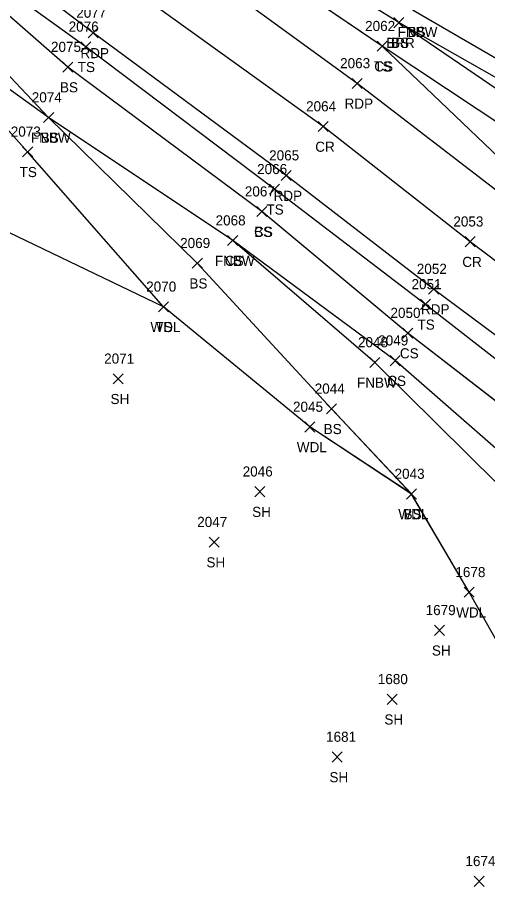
# Model space of a CAD drawing. Extents: x 1415642 to 1422021, y 544543 to 547232.
# Drawn here: x 1415773.3 to 1415866.3, y 546920.1 to 547093.4 of the extents above; entities that cross this region are included whole.
import ezdxf

# ---------------------------------------------------------------- set-up
doc = ezdxf.new("R2010")
doc.units = 0
for name, color, linetype in [('L_A', 7, 'Continuous'), ('L_I', 7, 'Continuous'), ('L_TIC', 7, 'Continuous'), ('LABL', 7, 'Continuous'), ('LAWA', 7, 'Continuous'), ('LELB', 7, 'Continuous'), ('LFNC', 7, 'Continuous'), ('P_A', 7, 'Continuous'), ('P_I', 7, 'Continuous'), ('P_TIC', 7, 'Continuous'), ('PET', 7, 'Continuous'), ('PRC', 7, 'Continuous')]:
    doc.layers.add(name, color=color, linetype=linetype)

msp = doc.modelspace()

# ---------------------------------------------------------------- linework, layer by layer
at = {"layer": 'L_TIC'}
for points in [[(1415847.8, 547091.4), (1415849.8, 547093.4)], [(1415849.8, 547091.4), (1415847.8, 547093.4)], [(1415847.8, 547091.4), (1415849.8, 547093.4)], [(1415849.8, 547091.4), (1415847.8, 547093.4)], [(1415785.82, 547086.62), (1415787.82, 547088.62)], [(1415787.82, 547086.62), (1415785.82, 547088.62)], [(1415844.5, 547086.74), (1415846.5, 547088.74)], [(1415846.5, 547086.74), (1415844.5, 547088.74)], [(1415844.5, 547086.74), (1415846.5, 547088.74)], [(1415846.5, 547086.74), (1415844.5, 547088.74)], [(1415782.27, 547082.61), (1415784.27, 547084.61)], [(1415784.27, 547082.61), (1415782.27, 547084.61)], [(1415778.47, 547072.63), (1415780.47, 547074.63)], [(1415780.47, 547072.63), (1415778.47, 547074.63)], [(1415778.47, 547072.63), (1415780.47, 547074.63)], [(1415780.47, 547072.63), (1415778.47, 547074.63)], [(1415774.31, 547065.85), (1415776.31, 547067.85)], [(1415776.31, 547065.85), (1415774.31, 547067.85)], [(1415823.18, 547058.44), (1415825.18, 547060.44)], [(1415825.18, 547058.44), (1415823.18, 547060.44)], [(1415820.69, 547054.02), (1415822.69, 547056.02)], [(1415822.69, 547054.02), (1415820.69, 547056.02)], [(1415820.69, 547054.02), (1415822.69, 547056.02)], [(1415822.69, 547054.02), (1415820.69, 547056.02)], [(1415814.91, 547048.29), (1415816.91, 547050.29)], [(1415816.91, 547048.29), (1415814.91, 547050.29)], [(1415814.91, 547048.29), (1415816.91, 547050.29)], [(1415816.91, 547048.29), (1415814.91, 547050.29)], [(1415807.9, 547043.81), (1415809.9, 547045.81)], [(1415809.9, 547043.81), (1415807.9, 547045.81)], [(1415801.21, 547035.19), (1415803.21, 547037.19)], [(1415803.21, 547035.19), (1415801.21, 547037.19)], [(1415801.21, 547035.19), (1415803.21, 547037.19)], [(1415803.21, 547035.19), (1415801.21, 547037.19)], [(1415853.08, 547035.67), (1415855.08, 547037.67)], [(1415855.08, 547035.67), (1415853.08, 547037.67)], [(1415849.56, 547029.99), (1415851.56, 547031.99)], [(1415851.56, 547029.99), (1415849.56, 547031.99)], [(1415843.05, 547024.19), (1415845.05, 547026.19)], [(1415845.05, 547024.19), (1415843.05, 547026.19)], [(1415847.06, 547024.54), (1415849.06, 547026.54)], [(1415849.06, 547024.54), (1415847.06, 547026.54)], [(1415792.23, 547020.95), (1415794.23, 547022.95)], [(1415794.23, 547020.95), (1415792.23, 547022.95)], [(1415834.48, 547015.01), (1415836.48, 547017.01)], [(1415836.48, 547015.01), (1415834.48, 547017.01)], [(1415830.18, 547011.42), (1415832.18, 547013.42)], [(1415832.18, 547011.42), (1415830.18, 547013.42)], [(1415820.27, 546998.62), (1415822.27, 547000.62)], [(1415822.27, 546998.62), (1415820.27, 547000.62)], [(1415850.29, 546998.16), (1415852.29, 547000.16)], [(1415852.29, 546998.16), (1415850.29, 547000.16)], [(1415850.29, 546998.16), (1415852.29, 547000.16)], [(1415852.29, 546998.16), (1415850.29, 547000.16)], [(1415811.22, 546988.64), (1415813.22, 546990.64)], [(1415813.22, 546988.64), (1415811.22, 546990.64)], [(1415861.73, 546978.72), (1415863.73, 546980.72)], [(1415863.73, 546978.72), (1415861.73, 546980.72)], [(1415855.85, 546971.2), (1415857.85, 546973.2)], [(1415857.85, 546971.2), (1415855.85, 546973.2)], [(1415846.46, 546957.55), (1415848.46, 546959.55)], [(1415848.46, 546957.55), (1415846.46, 546959.55)], [(1415835.57, 546946.14), (1415837.57, 546948.14)], [(1415837.57, 546946.14), (1415835.57, 546948.14)], [(1415863.72, 546921.55), (1415865.72, 546923.55)], [(1415865.72, 546921.55), (1415863.72, 546923.55)]]:
    msp.add_lwpolyline(points, dxfattribs=at)
at = {"layer": 'LABL'}
for points in [[(1415954.88, 547028.96), (1415919.29, 547048.67), (1415882.22, 547073.43), (1415848.8, 547092.4), (1415822.78, 547108.48), (1415823.18, 547113.64)], [(1415954.88, 547028.97), (1415919.29, 547048.66), (1415882.22, 547073.42), (1415848.8, 547092.4), (1415822.78, 547108.48), (1415823.18, 547113.63)]]:
    msp.add_lwpolyline(points, dxfattribs=at)
at = {"layer": 'LAWA'}
for points in [[(1415914.11, 546834.35), (1415931.31, 546850.74), (1415944.85, 546869.92), (1415908.68, 546903.98), (1415882.09, 546945.44), (1415862.73, 546979.72), (1415851.29, 546999.16), (1415831.18, 547012.42), (1415802.21, 547036.19), (1415763.17, 547054.94), (1415718.14, 547089.46), (1415689.93, 547108.01)], [(1415914.12, 546834.35), (1415931.31, 546850.75), (1415944.86, 546869.92), (1415908.68, 546903.98), (1415882.1, 546945.44), (1415862.73, 546979.72), (1415851.29, 546999.15), (1415831.18, 547012.42), (1415802.2, 547036.19), (1415763.17, 547054.94), (1415718.15, 547089.45), (1415689.93, 547108.01)]]:
    msp.add_lwpolyline(points, dxfattribs=at)
at = {"layer": 'LELB'}
for points in [[(1415821.69, 547055.02), (1415783.27, 547083.61), (1415741.01, 547120.53), (1415723.94, 547132.39), (1415695.54, 547155.33), (1415675.42, 547170.57)], [(1415821.7, 547055.02), (1415783.28, 547083.61), (1415741.01, 547120.53), (1415723.94, 547132.38), (1415695.54, 547155.33), (1415675.42, 547170.56)], [(1415851.29, 546999.16), (1415835.48, 547016.01), (1415808.9, 547044.81), (1415779.47, 547073.63), (1415738.35, 547117.19), (1415722.7, 547128.21), (1415693.4, 547151.97), (1415674.17, 547168.64)], [(1415851.29, 546999.15), (1415835.48, 547016.02), (1415808.9, 547044.81), (1415779.47, 547073.63), (1415738.34, 547117.19), (1415722.7, 547128.21), (1415693.4, 547151.96), (1415674.17, 547168.64)], [(1415802.21, 547036.19), (1415775.31, 547066.85), (1415750.83, 547094.22), (1415733.1, 547115.73), (1415720.57, 547124.98), (1415690.99, 547148.71), (1415672.49, 547166.01)], [(1415802.2, 547036.19), (1415775.31, 547066.86), (1415750.83, 547094.23), (1415733.1, 547115.73), (1415720.57, 547124.98), (1415690.99, 547148.71), (1415672.49, 547166.01)], [(1416091.47, 546896.23), (1416067.28, 546915.33), (1416036.7, 546941.48), (1416008.25, 546963.65), (1415975.6, 546988.56), (1415942.26, 547013.09), (1415909.12, 547036.86), (1415872.92, 547061.56), (1415845.5, 547087.74), (1415809.03, 547112.5), (1415805.73, 547114.89), (1415787.7, 547125.97), (1415788.24, 547129.84), (1415790.68, 547131.85)], [(1416091.47, 546896.23), (1416067.28, 546915.33), (1416036.71, 546941.48), (1416008.26, 546963.65), (1415975.6, 546988.56), (1415942.26, 547013.09), (1415909.12, 547036.86), (1415872.92, 547061.56), (1415845.5, 547087.74), (1415809.04, 547112.5), (1415805.73, 547114.9), (1415787.7, 547125.97), (1415788.24, 547129.84), (1415790.68, 547131.85)], [(1415979.27, 546932.57), (1415964.6, 546940.59), (1415957.63, 546956.7), (1415934.73, 546972.98), (1415912.21, 546991.17), (1415886.95, 547011.09), (1415854.08, 547036.67), (1415824.18, 547059.44), (1415786.82, 547087.62), (1415741.01, 547120.53)], [(1415979.28, 546932.57), (1415964.61, 546940.59), (1415957.63, 546956.7), (1415934.74, 546972.98), (1415912.22, 546991.17), (1415886.96, 547011.09), (1415854.08, 547036.67), (1415824.19, 547059.44), (1415786.82, 547087.62), (1415741.01, 547120.53)], [(1416166.26, 546865.71), (1416159.51, 546874.18), (1416128.86, 546893.05), (1416099.94, 546911.95), (1416080.11, 546927.17), (1416051.61, 546951.27), (1416024.79, 546978.54), (1415989.85, 547005.5), (1415949.92, 547022.61), (1415918.77, 547047.8), (1415880.24, 547071.02), (1415848.8, 547092.4)], [(1416166.26, 546865.71), (1416159.51, 546874.18), (1416128.86, 546893.05), (1416099.95, 546911.94), (1416080.11, 546927.17), (1416051.61, 546951.27), (1416024.79, 546978.54), (1415989.85, 547005.5), (1415949.92, 547022.61), (1415918.78, 547047.8), (1415880.25, 547071.01), (1415848.8, 547092.4)], [(1416210.45, 546810.14), (1416187.24, 546828.5), (1416172.35, 546839.03), (1416162.91, 546845.64), (1416145.69, 546861.76), (1416125.16, 546875.54), (1416093.4, 546901.43), (1416075.19, 546919.9), (1416045.66, 546942.32), (1416039.77, 546946.29), (1416015.88, 546971.97), (1415979.91, 546993.7), (1415946.5, 547018.2), (1415914.22, 547042.27), (1415877.25, 547066.68), (1415845.5, 547087.74)], [(1416210.45, 546810.14), (1416187.24, 546828.5), (1416172.36, 546839.03), (1416162.91, 546845.64), (1416145.7, 546861.76), (1416125.16, 546875.54), (1416093.4, 546901.44), (1416075.18, 546919.9), (1416045.66, 546942.32), (1416039.77, 546946.29), (1416015.88, 546971.97), (1415979.91, 546993.7), (1415946.51, 547018.2), (1415914.22, 547042.27), (1415877.24, 547066.68), (1415845.5, 547087.74)], [(1416200.69, 546756.25), (1416177.76, 546767.63), (1416166.72, 546775.57), (1416158.94, 546780.74), (1416149.8, 546790.95), (1416145.27, 546792.19), (1416135.47, 546803.24), (1416119.09, 546819.38), (1416087.86, 546845.73), (1416058.66, 546867.92), (1416017.63, 546898.15), (1415975.94, 546926.54), (1415961.59, 546937.35), (1415930.25, 546967.22), (1415904.85, 546987.6), (1415883.27, 547005.7), (1415850.56, 547030.99), (1415821.69, 547055.02)], [(1416200.69, 546756.25), (1416177.77, 546767.63), (1416166.72, 546775.57), (1416158.93, 546780.74), (1416149.8, 546790.95), (1416145.28, 546792.19), (1416135.47, 546803.24), (1416119.09, 546819.38), (1416087.87, 546845.73), (1416058.67, 546867.92), (1416017.63, 546898.16), (1415975.95, 546926.55), (1415961.6, 546937.34), (1415930.25, 546967.22), (1415904.86, 546987.6), (1415883.28, 547005.7), (1415850.57, 547030.99), (1415821.7, 547055.02)], [(1415881.61, 546996.31), (1415848.06, 547025.54), (1415815.91, 547049.29)], [(1415881.62, 546996.31), (1415848.06, 547025.54), (1415815.91, 547049.29)]]:
    msp.add_lwpolyline(points, dxfattribs=at)
at = {"layer": 'LFNC'}
for points in [[(1416067.58, 546984.06), (1416031.2, 546999.34), (1415996.11, 547015.1), (1415957.45, 547035.03), (1415922.34, 547052.78), (1415883.85, 547076.17), (1415852.09, 547094.57), (1415823.18, 547113.63), (1415819.4, 547116.14), (1415815.46, 547118.48), (1415790.83, 547135.32)], [(1416067.58, 546984.06), (1416031.2, 546999.34), (1415996.12, 547015.09), (1415957.45, 547035.03), (1415922.34, 547052.78), (1415883.85, 547076.17), (1415852.09, 547094.57), (1415823.18, 547113.64), (1415819.41, 547116.14), (1415815.45, 547118.48), (1415790.83, 547135.32)], [(1415844.05, 547025.19), (1415815.91, 547049.29), (1415779.47, 547073.63), (1415750.83, 547094.22), (1415737.47, 547104.24)], [(1415844.05, 547025.19), (1415815.91, 547049.29), (1415779.47, 547073.63), (1415750.83, 547094.23), (1415737.47, 547104.24)], [(1415844.05, 547025.19), (1415874.55, 546995.04)], [(1415844.05, 547025.19), (1415874.56, 546995.04)]]:
    msp.add_lwpolyline(points, dxfattribs=at)
at = {"layer": 'P_TIC'}
for points in [[(1415787.27, 547089.37), (1415789.27, 547091.37)], [(1415789.27, 547089.37), (1415787.27, 547091.37)], [(1415839.56, 547079.38), (1415841.56, 547081.38)], [(1415841.56, 547079.38), (1415839.56, 547081.38)], [(1415832.81, 547070.85), (1415834.81, 547072.85)], [(1415834.81, 547070.85), (1415832.81, 547072.85)], [(1415825.51, 547061.15), (1415827.51, 547063.15)], [(1415827.51, 547061.15), (1415825.51, 547063.15)], [(1415861.93, 547048.07), (1415863.93, 547050.07)], [(1415863.93, 547048.07), (1415861.93, 547050.07)], [(1415854.69, 547038.7), (1415856.69, 547040.7)], [(1415856.69, 547038.7), (1415854.69, 547040.7)]]:
    msp.add_lwpolyline(points, dxfattribs=at)
at = {"layer": 'PET'}
for points in [[(1415969.06, 546981.93), (1415936.64, 547006.92), (1415904.27, 547031.49), (1415869.9, 547057.78), (1415840.56, 547080.38), (1415803.16, 547107.61), (1415784.15, 547121.85), (1415763.35, 547137.62), (1415738.26, 547155), (1415710.8, 547176.64), (1415691.9, 547191.05)], [(1415969.07, 546981.93), (1415936.65, 547006.92), (1415904.27, 547031.49), (1415869.9, 547057.78), (1415840.56, 547080.38), (1415803.16, 547107.61), (1415784.15, 547121.85), (1415763.35, 547137.62), (1415738.26, 547155), (1415710.8, 547176.64), (1415691.9, 547191.04)], [(1415982.21, 546942.39), (1415954.4, 546964.56), (1415923.45, 546987.94), (1415890.93, 547013.5), (1415855.69, 547039.7), (1415826.51, 547062.15), (1415788.27, 547090.37), (1415749.29, 547120.02), (1415723.83, 547138.72), (1415697.43, 547158.88), (1415677.46, 547174.08)], [(1415982.21, 546942.39), (1415954.4, 546964.56), (1415923.45, 546987.94), (1415890.93, 547013.5), (1415855.69, 547039.7), (1415826.51, 547062.15), (1415788.27, 547090.37), (1415749.28, 547120.03), (1415723.83, 547138.72), (1415697.43, 547158.88), (1415677.46, 547174.08)]]:
    msp.add_lwpolyline(points, dxfattribs=at)
at = {"layer": 'PRC'}
for points in [[(1415989.92, 546951.68), (1415962.46, 546973.18), (1415930.15, 546997.68), (1415898.02, 547022.56), (1415862.93, 547049.07), (1415833.82, 547071.85), (1415795.61, 547099.36), (1415756.73, 547129.15), (1415731.28, 547147.85), (1415704.22, 547168.12), (1415684.99, 547182.73)], [(1415989.92, 546951.67), (1415962.46, 546973.18), (1415930.15, 546997.68), (1415898.02, 547022.56), (1415862.93, 547049.07), (1415833.81, 547071.85), (1415795.61, 547099.36), (1415756.73, 547129.15), (1415731.28, 547147.85), (1415704.22, 547168.13), (1415684.99, 547182.72)]]:
    msp.add_lwpolyline(points, dxfattribs=at)

# ---------------------------------------------------------------- texts
at = {"layer": 'L_A'}
for s, p in [('FNBW', (1415848.56, 547089.57)), ('BS', (1415850.53, 547089.57)), ('BRR', (1415846.29, 547087.4)), ('BS', (1415847.24, 547087.4)), ('TS', (1415785.23, 547082.62)), ('TS', (1415843.91, 547082.74)), ('CS', (1415843.94, 547082.74)), ('BS', (1415781.71, 547078.61)), ('FNBW', (1415775.94, 547068.63)), ('BS', (1415777.91, 547068.63)), ('TS', (1415773.72, 547061.85)), ('TS', (1415822.59, 547054.44)), ('CS', (1415820.14, 547050.02)), ('BS', (1415820.14, 547050.02)), ('FNBW', (1415812.38, 547044.29)), ('CS', (1415814.35, 547044.29)), ('BS', (1415807.34, 547039.81)), ('WDL', (1415799.62, 547031.19)), ('TS', (1415800.61, 547031.19)), ('TS', (1415852.49, 547031.67)), ('CS', (1415849.01, 547025.99)), ('FNBW', (1415840.52, 547020.19)), ('CS', (1415846.5, 547020.54)), ('SH', (1415791.72, 547016.95)), ('BS', (1415833.92, 547011.01)), ('WDL', (1415828.6, 547007.42)), ('SH', (1415819.76, 546994.62)), ('WDL', (1415848.7, 546994.16)), ('BS', (1415849.73, 546994.16)), ('SH', (1415810.71, 546984.64)), ('WDL', (1415860.15, 546974.72)), ('SH', (1415855.34, 546967.2)), ('SH', (1415845.94, 546953.55)), ('SH', (1415835.06, 546942.14))]:
    msp.add_text(s, height=2, dxfattribs=at).set_placement(p)
at = {"layer": 'L_I'}
for s, p in [('2076', (1415783.43, 547090.62)), ('2062', (1415842.12, 547090.74)), ('2062', (1415842.12, 547090.74)), ('2075', (1415779.93, 547086.61)), ('2074', (1415776.13, 547076.63)), ('2074', (1415776.13, 547076.63)), ('2073', (1415771.97, 547069.85)), ('2066', (1415820.74, 547062.44)), ('2067', (1415818.31, 547058.02)), ('2067', (1415818.31, 547058.02)), ('2068', (1415812.52, 547052.29)), ('2068', (1415812.52, 547052.29)), ('2069', (1415805.5, 547047.81)), ('2051', (1415851.31, 547039.67)), ('2070', (1415798.78, 547039.19)), ('2070', (1415798.78, 547039.19)), ('2050', (1415847.14, 547033.99)), ('2048', (1415840.71, 547028.19)), ('2049', (1415844.71, 547028.54)), ('2071', (1415790.46, 547024.95)), ('2044', (1415832.14, 547019.01)), ('2045', (1415827.84, 547015.42)), ('2046', (1415817.88, 547002.62)), ('2043', (1415847.95, 547002.16)), ('2043', (1415847.95, 547002.16)), ('2047', (1415808.88, 546992.64)), ('1678', (1415859.99, 546982.72)), ('1679', (1415854.1, 546975.2)), ('1680', (1415844.63, 546961.55)), ('1681', (1415834.39, 546950.14)), ('1674', (1415861.98, 546925.55))]:
    msp.add_text(s, height=2, dxfattribs=at).set_placement(p)
at = {"layer": 'P_A'}
for s, p in [('RDP', (1415785.76, 547085.37)), ('RDP', (1415838.05, 547075.38)), ('CR', (1415832.25, 547066.85)), ('RDP', (1415824, 547057.15)), ('CR', (1415861.36, 547044.07)), ('RDP', (1415853.18, 547034.7))]:
    msp.add_text(s, height=2, dxfattribs=at).set_placement(p)
at = {"layer": 'P_I'}
for s, p in [('2077', (1415784.93, 547093.37)), ('2063', (1415837.17, 547083.38)), ('2064', (1415830.43, 547074.85)), ('2065', (1415823.12, 547065.15)), ('2053', (1415859.59, 547052.07)), ('2052', (1415852.35, 547042.7))]:
    msp.add_text(s, height=2, dxfattribs=at).set_placement(p)

doc.saveas('drawing.dxf')
